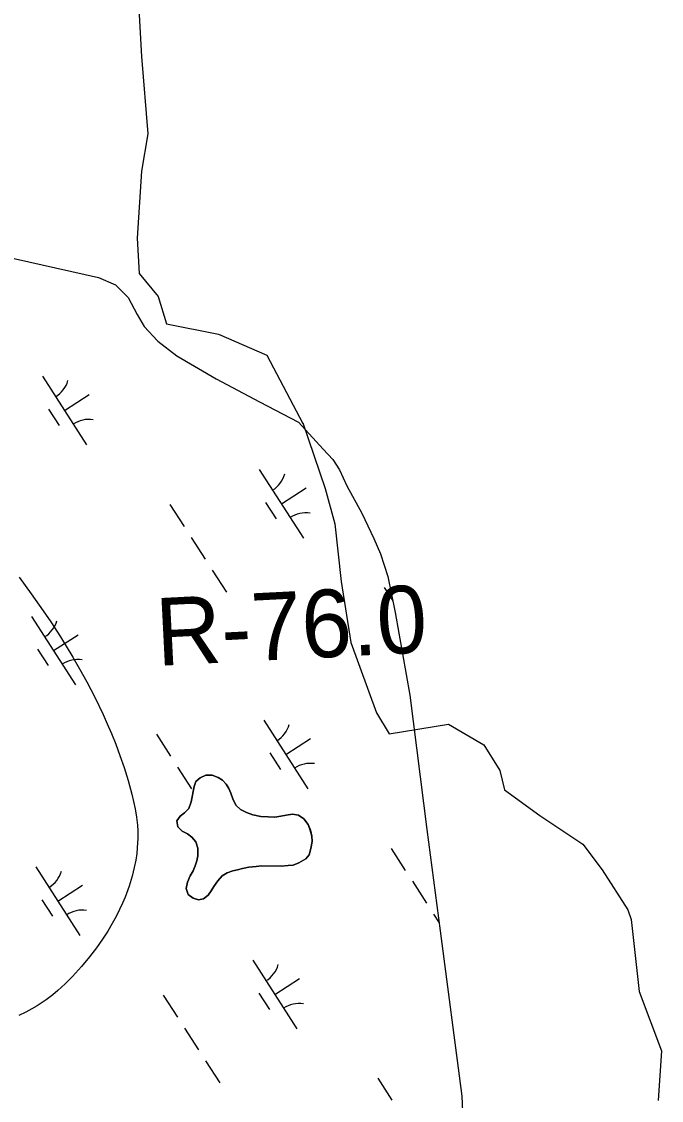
# Model space of a CAD drawing. Extents: x 3937982 to 3958556, y 219448 to 241894.
# Drawn here: x 3947419 to 3947811, y 232047 to 232709 of the extents above; entities that cross this region are included whole.
import ezdxf

# ---------------------------------------------------------------- set-up
doc = ezdxf.new("R2010")
doc.units = 0
for name, color, linetype in [('V-RIVR-EDGE', 7, 'Continuous'), ('V-RIVR-RANG-IDEN', 7, 'Continuous'), ('V-SITE-VEGE', 7, 'Continuous'), ('V-TOPO-SHOR', 7, 'Continuous'), ('V-WETL-SWMP', 7, 'Continuous')]:
    doc.layers.add(name, color=color, linetype=linetype)

msp = doc.modelspace()

# ---------------------------------------------------------------- linework, layer by layer
at = {"layer": 'V-RIVR-EDGE'}
for points in [[(3947553.741, 232989.149), (3947546.694, 232987.227), (3947535.803, 232963.524), (3947535.162, 232950.07), (3947534.522, 232931.492), (3947516.584, 232911.953), (3947496.084, 232892.734), (3947481.99, 232879.921), (3947480.709, 232860.702), (3947470.458, 232813.295), (3947470.458, 232783.826), (3947483.271, 232746.669), (3947490.959, 232713.357), (3947492.24, 232687.731), (3947496.084, 232640.324), (3947492.24, 232617.262), (3947489.677, 232576.261), (3947490.959, 232554.48), (3947502.49, 232540.386), (3947507.615, 232523.729), (3947539.647, 232517.323), (3947569.116, 232504.51), (3947591.378, 232462.549)], [(3947591.231, 232462.878), (3947604.992, 232422.58), (3947610.889, 232400.956), (3947614.821, 232365.572), (3947620.718, 232328.222), (3947636.444, 232284.974), (3947644.307, 232272.197), (3947680.675, 232278.094), (3947702.298, 232265.316), (3947712.127, 232249.59), (3947715.076, 232237.795), (3947736.7, 232222.069), (3947763.238, 232204.377), (3947775.033, 232188.651), (3947790.759, 232164.078), (3947792.725, 232158.181), (3947797.639, 232113.95), (3947811.4, 232077.583), (3947809.434, 232047.114)]]:
    msp.add_lwpolyline(points, dxfattribs=at)
at = {"layer": 'V-SITE-VEGE'}
msp.add_lwpolyline([(3947417.118, 232368.262), (3947424.667, 232358.003), (3947431.929, 232347.692), (3947436.599, 232340.79), (3947442.604, 232331.558), (3947450.187, 232319.196), (3947454.294, 232312.108), (3947458.777, 232303.987), (3947463.61, 232294.685), (3947468.742, 232284.028), (3947471.3, 232278.332), (3947473.889, 232272.252), (3947476.484, 232265.757), (3947479.06, 232258.821), (3947481.581, 232251.417), (3947484.01, 232243.514), (3947486.29, 232235.076), (3947488.358, 232226.073), (3947489.226, 232221.109), (3947489.783, 232216.091), (3947489.978, 232212.72), (3947490.027, 232208.196), (3947489.72, 232202.122), (3947489.353, 232198.63), (3947488.77, 232194.626), (3947487.887, 232190.035), (3947486.599, 232184.775), (3947484.772, 232178.752), (3947482.222, 232171.873), (3947480.668, 232168.207), (3947478.859, 232164.306), (3947476.764, 232160.152), (3947474.342, 232155.739), (3947471.546, 232151.053), (3947468.329, 232146.089), (3947464.632, 232140.831), (3947460.393, 232135.279), (3947455.541, 232129.432), (3947449.999, 232123.284), (3947445.454, 232118.703), (3947440.879, 232114.57), (3947437.811, 232112.047), (3947433.697, 232108.952), (3947428.163, 232105.27), (3947424.974, 232103.374), (3947421.309, 232101.377), (3947417.084, 232099.298)], dxfattribs=at)
at = {"layer": 'V-TOPO-SHOR'}
for points in [[(3947388.42, 232569.509), (3947465.861, 232552.213), (3947476.293, 232547.525), (3947484.065, 232539.901), (3947489.697, 232529.331), (3947493.976, 232522.101), (3947502.252, 232513.072), (3947514.028, 232503.993), (3947538.155, 232489.854), (3947564.734, 232475.856), (3947588.708, 232463.293), (3947603.853, 232446.85)], [(3947565.944, 232191.145), (3947562.754, 232190.792), (3947558.125, 232190.266), (3947554.3, 232189.588), (3947551.273, 232188.759), (3947548.246, 232188.089), (3947544.901, 232186.938), (3947541.887, 232184.99), (3947539.044, 232181.927), (3947536.683, 232178.39), (3947535.112, 232175.817), (3947533.222, 232173.083), (3947530.369, 232170.978), (3947527.342, 232170.308), (3947523.977, 232171.232), (3947520.917, 232173.597), (3947519.762, 232177.259), (3947520.524, 232181.099), (3947522.08, 232184.949), (3947523.965, 232188.163), (3947525.212, 232191.21), (3947526.299, 232194.258), (3947526.908, 232197.299), (3947526.86, 232201.929), (3947525.544, 232205.911), (3947523.119, 232208.76), (3947520.54, 232210.812), (3947517.331, 232212.374), (3947514.589, 232215.063), (3947514.073, 232218.731), (3947516.119, 232221.627), (3947518.654, 232223.571), (3947521.343, 232226.313), (3947522.74, 232230.321), (3947523.346, 232233.522), (3947523.952, 232236.723), (3947524.561, 232239.762), (3947525.648, 232242.81), (3947528.339, 232245.232), (3947531.679, 232246.703), (3947535.671, 232246.744), (3947539.359, 232245.343), (3947541.932, 232243.772), (3947544.193, 232241.239), (3947545.819, 232238.539), (3947547.123, 232235.678), (3947548.438, 232232.178), (3947550.232, 232228.363), (3947552.977, 232225.674), (3947556.669, 232223.796), (3947560.677, 232222.397), (3947565.478, 232221.488), (3947569.952, 232221.213), (3947574.108, 232221.097), (3947577.776, 232221.613), (3947581.122, 232222.287), (3947584.952, 232222.805), (3947588.63, 232222.203), (3947591.848, 232219.999), (3947594.598, 232216.511), (3947595.913, 232213.011), (3947596.908, 232209.347), (3947597.101, 232205.995), (3947596.185, 232201.833), (3947595.106, 232197.987), (3947593.216, 232195.413), (3947588.927, 232192.974), (3947585.425, 232191.661), (3947582.394, 232191.311), (3947578.085, 232190.946), (3947565.944, 232191.145)]]:
    msp.add_lwpolyline(points, dxfattribs=at)
at = {"layer": 'V-WETL-SWMP'}
for p, q in [((3947431.462, 232491.553), (3947458.524, 232449.51)), ((3947444.993, 232470.532), (3947460.128, 232480.274)), ((3947435.258, 232471.401), (3947441.752, 232461.311)), ((3947564.591, 232434.255), (3947591.653, 232392.212)), ((3947578.122, 232413.233), (3947593.257, 232422.976)), ((3947509.725, 232412.858), (3947518.385, 232399.404)), ((3947568.387, 232414.102), (3947574.882, 232404.012)), ((3947522.715, 232392.677), (3947531.375, 232379.223)), ((3947535.705, 232372.496), (3947544.364, 232359.042)), ((3947641.292, 232361.97), (3947646.545, 232353.808)), ((3947424.724, 232344.225), (3947451.786, 232302.182)), ((3947438.255, 232323.204), (3947453.39, 232332.946)), ((3947428.52, 232324.073), (3947435.014, 232313.982)), ((3947567.289, 232280.535), (3947594.352, 232238.492)), ((3947501.424, 232271.94), (3947510.084, 232258.486)), ((3947580.821, 232259.513), (3947595.956, 232269.256)), ((3947571.085, 232260.383), (3947577.58, 232250.292)), ((3947514.414, 232251.759), (3947523.074, 232238.306)), ((3947645.553, 232201.839), (3947654.213, 232188.386)), ((3947427.422, 232190.506), (3947454.484, 232148.462)), ((3947440.953, 232169.484), (3947456.089, 232179.226)), ((3947658.542, 232181.659), (3947667.202, 232168.205)), ((3947431.218, 232170.353), (3947437.713, 232160.263)), ((3947671.532, 232161.478), (3947674.976, 232156.128)), ((3947560.551, 232133.207), (3947587.614, 232091.164)), ((3947574.083, 232112.185), (3947589.218, 232121.928)), ((3947564.347, 232113.055), (3947570.842, 232102.964)), ((3947505.685, 232111.81), (3947514.345, 232098.356)), ((3947518.675, 232091.629), (3947527.335, 232078.175)), ((3947531.665, 232071.448), (3947540.325, 232057.995)), ((3947637.252, 232060.922), (3947645.912, 232047.468))]:
    msp.add_line(p, q, dxfattribs=at)
for points in [[(3947388.42, 232569.509), (3947465.861, 232552.213), (3947476.294, 232547.526), (3947484.065, 232539.901), (3947489.698, 232529.331)], [(3947489.698, 232529.331), (3947493.975, 232522.102), (3947502.252, 232513.071), (3947514.027, 232503.993), (3947538.155, 232489.853), (3947564.734, 232475.856), (3947588.708, 232463.293), (3947603.853, 232446.85), (3947609.745, 232440.384), (3947613.77, 232434.132), (3947618.297, 232424.389), (3947627.558, 232407.469), (3947634.94, 232391.929), (3947638.996, 232382.648), (3947643.565, 232368.71), (3947647.984, 232346.614), (3947656.887, 232295.897), (3947667.51, 232213.501), (3947675.597, 232151.356), (3947688.976, 232049.877), (3947691.131, 231998.159)]]:
    msp.add_lwpolyline(points, dxfattribs=at)
msp.add_lwpolyline([(3947565.944, 232191.144), (3947578.086, 232190.947), (3947582.395, 232191.311), (3947585.426, 232191.661), (3947588.927, 232192.974), (3947593.215, 232195.413), (3947595.106, 232197.988), (3947596.185, 232201.833), (3947597.101, 232205.995), (3947596.908, 232209.347), (3947595.912, 232213.011), (3947594.599, 232216.512), (3947591.848, 232219.998), (3947588.631, 232222.202), (3947584.951, 232222.804), (3947581.123, 232222.286), (3947577.775, 232221.613), (3947574.107, 232221.096), (3947569.953, 232221.214), (3947565.477, 232221.488), (3947560.676, 232222.398), (3947556.669, 232223.795), (3947552.976, 232225.674), (3947550.233, 232228.362), (3947548.438, 232232.178), (3947547.124, 232235.678), (3947545.818, 232238.54), (3947544.193, 232241.239), (3947541.931, 232243.772), (3947539.359, 232245.343), (3947535.671, 232246.744), (3947531.679, 232246.703), (3947528.339, 232245.232), (3947525.648, 232242.809), (3947524.561, 232239.763), (3947523.953, 232236.722), (3947523.346, 232233.521), (3947522.74, 232230.32), (3947521.343, 232226.313), (3947518.655, 232223.57), (3947516.119, 232221.628), (3947514.072, 232218.732), (3947514.588, 232215.063), (3947517.331, 232212.375), (3947520.541, 232210.811), (3947523.118, 232208.76), (3947525.543, 232205.91), (3947526.861, 232201.93), (3947526.908, 232197.298), (3947526.299, 232194.257), (3947525.212, 232191.211), (3947523.965, 232188.163), (3947522.081, 232184.95), (3947520.523, 232181.1), (3947519.763, 232177.259), (3947520.918, 232173.597), (3947523.977, 232171.232), (3947527.341, 232170.308), (3947530.369, 232170.977), (3947533.222, 232173.083), (3947535.112, 232175.817), (3947536.683, 232178.389), (3947539.043, 232181.927), (3947541.887, 232184.99), (3947544.902, 232186.938), (3947548.245, 232188.09), (3947551.273, 232188.759), (3947554.3, 232189.589), (3947558.126, 232190.266), (3947562.753, 232190.792)], close=True, dxfattribs=at)
for centre, start, end in [((3947430.242, 232493.886), 301.99668, 343.540338), ((3947460.142, 232447.434), 81.996677, 123.540335), ((3947563.372, 232436.588), 301.99668, 343.540338), ((3947593.272, 232390.136), 81.996677, 123.540335), ((3947423.504, 232346.558), 301.99668, 343.540338), ((3947453.404, 232300.106), 81.996677, 123.540335), ((3947566.07, 232282.868), 301.99668, 343.540338), ((3947595.97, 232236.416), 81.996677, 123.540335), ((3947426.203, 232192.838), 301.99668, 343.540338), ((3947456.103, 232146.387), 81.996677, 123.540335), ((3947559.332, 232135.54), 301.99668, 343.540338), ((3947589.232, 232089.088), 81.996677, 123.540335)]:
    msp.add_arc(centre, 17.623, start, end, dxfattribs=at)

# ---------------------------------------------------------------- texts
at = {"layer": 'V-RIVR-RANG-IDEN'}
msp.add_text('R-76.0', height=41.5, rotation=2.909389, dxfattribs=at).set_placement((3947502.104, 232313.807))

doc.saveas('drawing.dxf')
